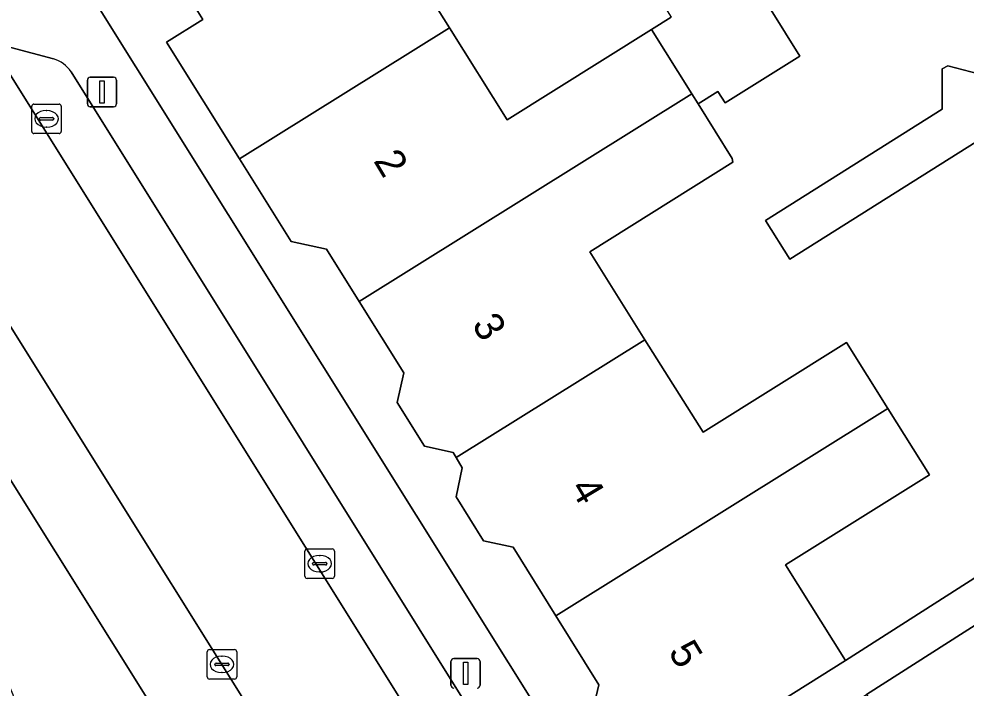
# Model space of a CAD drawing. Extents: x 159664 to 160323, y 385312 to 386115.
# Drawn here: x 159927.2 to 159959.3, y 386010.94 to 386033.62 of the extents above; entities that cross this region are included whole.
import ezdxf

# ---------------------------------------------------------------- set-up
doc = ezdxf.new("R2010")
doc.units = 0
for name, color, linetype in [('IMGEO_Erf', 7, 'Continuous'), ('IMGEO_Groenvoorziening', 7, 'Continuous'), ('IMGEO_Kolk', 7, 'Continuous'), ('IMGEO_Lichtmast', 7, 'Continuous'), ('IMGEO_Pand', 7, 'Continuous'), ('IMGEO_Pand_nummerreeks', 7, 'Continuous'), ('IMGEO_Parkeervlak_open', 7, 'Continuous'), ('IMGEO_Rijbaan_lokaal_open', 7, 'Continuous'), ('IMGEO_Voetpad_open', 7, 'Continuous')]:
    doc.layers.add(name, color=color, linetype=linetype)

msp = doc.modelspace()

# ---------------------------------------------------------------- linework, layer by layer
at = {"layer": 'IMGEO_Erf'}
for points in [[(159927.976, 386037.096), (159946.972, 386006.7), (159948.83, 386007.861), (159948.549, 386008.326), (159947.541, 386008.556), (159946.616, 386010.041), (159946.849, 386011.045), (159945.393, 386013.39), (159943.948, 386015.714), (159942.944, 386015.931), (159942.014, 386017.42), (159942.223, 386018.408), (159942.016, 386018.757), (159941.918, 386018.918), (159940.946, 386019.132), (159940.01, 386020.621), (159940.236, 386021.621), (159938.725, 386024.043), (159937.62, 386025.809), (159936.426, 386026.073), (159934.676, 386028.873), (159932.199, 386032.828), (159933.429, 386033.597), (159932.181, 386035.593)], [(159950.63, 386037.227), (159953.666, 386032.36), (159951.127, 386030.771), (159950.886, 386031.154), (159950.214, 386030.738), (159951.368, 386028.891), (159951.396, 386028.767), (159946.543, 386025.72), (159948.41, 386022.746), (159950.381, 386019.607), (159955.244, 386022.646), (159956.645, 386020.41), (159958.054, 386018.161), (159953.175, 386015.113), (159955.207, 386011.867), (159970.237, 386021.476)], [(159940.008, 386036.162), (159941.792, 386033.312), (159943.743, 386030.195), (159948.638, 386033.259), (159949.303, 386033.675)], [(159964.428, 386032.462), (159953.326, 386025.476), (159952.501, 386026.788), (159958.488, 386030.555), (159958.488, 386031.92), (159958.682, 386032.029), (159959.973, 386031.691)], [(159972.471, 386021.286), (159955.923, 386010.723), (159957.939, 386007.502), (159962.821, 386010.541)]]:
    msp.add_lwpolyline(points, dxfattribs=at)
at = {"layer": 'IMGEO_Groenvoorziening'}
msp.add_lwpolyline([(159955.282, 385972.677), (159935.869, 386003.671), (159924.707, 386021.493), (159923.616, 386016.481), (159926.674, 386011.449), (159926.994, 386010.725), (159927.155, 386009.956), (159927.153, 386009.17), (159926.987, 386008.402), (159926.418, 386007.571), (159928.912, 386004.426), (159932.034, 386000), (159933.824, 385997.462), (159936.786, 385992.325), (159938.156, 385989.949)], dxfattribs=at)
at = {"layer": 'IMGEO_Kolk'}
for p, q in [((159927.631, 386029.805), (159927.631, 386030.657)), ((159927.706, 386030.731), (159928.558, 386030.731)), ((159928.632, 386030.657), (159928.632, 386029.805)), ((159928.119, 386030.511), (159928.144, 386030.511)), ((159927.89, 386030.225), (159927.89, 386030.237)), ((159928.328, 386030.188), (159927.93, 386030.188)), ((159927.933, 386030.274), (159928.331, 386030.274)), ((159928.374, 386030.237), (159928.374, 386030.225)), ((159928.558, 386029.731), (159927.706, 386029.731)), ((159928.142, 386029.951), (159928.117, 386029.951)), ((159936.889, 386014.727), (159936.889, 386015.579)), ((159936.964, 386015.653), (159937.816, 386015.653)), ((159937.89, 386015.579), (159937.89, 386014.727)), ((159937.191, 386015.196), (159937.589, 386015.196)), ((159937.377, 386015.433), (159937.402, 386015.433)), ((159937.148, 386015.147), (159937.148, 386015.159)), ((159937.586, 386015.11), (159937.188, 386015.11)), ((159937.4, 386014.873), (159937.375, 386014.873)), ((159937.632, 386015.159), (159937.632, 386015.147)), ((159937.816, 386014.653), (159936.964, 386014.653)), ((159933.576, 386011.316), (159933.576, 386012.168)), ((159933.651, 386012.242), (159934.503, 386012.242)), ((159934.064, 386012.022), (159934.089, 386012.022)), ((159934.577, 386012.168), (159934.577, 386011.316)), ((159933.835, 386011.736), (159933.835, 386011.748)), ((159934.273, 386011.699), (159933.875, 386011.699)), ((159933.878, 386011.785), (159934.276, 386011.785)), ((159934.319, 386011.748), (159934.319, 386011.736)), ((159934.087, 386011.462), (159934.062, 386011.462)), ((159934.503, 386011.242), (159933.651, 386011.242))]:
    msp.add_line(p, q, dxfattribs=at)
for points in [[(159927.631, 386029.805), (159927.631, 386030.657)], [(159927.706, 386030.731), (159928.558, 386030.731)], [(159928.632, 386030.657), (159928.632, 386029.805)], [(159928.558, 386029.731), (159927.706, 386029.731)], [(159936.889, 386014.727), (159936.889, 386015.579)], [(159936.964, 386015.653), (159937.816, 386015.653)], [(159937.89, 386015.579), (159937.89, 386014.727)], [(159937.816, 386014.653), (159936.964, 386014.653)], [(159933.576, 386011.316), (159933.576, 386012.168)], [(159933.651, 386012.242), (159934.503, 386012.242)], [(159934.577, 386012.168), (159934.577, 386011.316)], [(159934.503, 386011.242), (159933.651, 386011.242)]]:
    msp.add_lwpolyline(points, dxfattribs=at)
for centre, radius, start, end in [((159927.708, 386030.655), 0.0765, 91.552, 178.448), ((159927.708, 386030.655), 0.0765, 91.552, 178.448), ((159928.556, 386030.655), 0.0765, 1.552, 88.448), ((159928.556, 386030.655), 0.0765, 1.552, 88.448), ((159927.93, 386030.234), 0.0403, 85.8775, 175.7526), ((159927.927, 386030.224), 0.0366, 178.938, 274.7102), ((159928.331, 386030.231), 0.043, 264.8664, 352.4533), ((159928.335, 386030.236), 0.0386, 1.7309, 96.639), ((159927.708, 386029.807), 0.0765, 181.552, 268.448), ((159927.708, 386029.807), 0.0765, 181.552, 268.448), ((159928.556, 386029.807), 0.0765, 271.552, 358.448), ((159928.556, 386029.807), 0.0765, 271.552, 358.448), ((159936.966, 386015.577), 0.0765, 91.552, 178.448), ((159936.966, 386015.577), 0.0765, 91.552, 178.448), ((159937.814, 386015.577), 0.0765, 1.552, 88.448), ((159937.814, 386015.577), 0.0765, 1.552, 88.448), ((159937.188, 386015.156), 0.0403, 85.8775, 175.7526), ((159937.593, 386015.158), 0.0386, 1.7309, 96.639), ((159937.185, 386015.146), 0.0366, 178.938, 274.7102), ((159937.589, 386015.153), 0.043, 264.8664, 352.4533), ((159936.966, 386014.729), 0.0765, 181.552, 268.448), ((159936.966, 386014.729), 0.0765, 181.552, 268.448), ((159937.814, 386014.729), 0.0765, 271.552, 358.448), ((159937.814, 386014.729), 0.0765, 271.552, 358.448), ((159933.653, 386012.166), 0.0765, 91.552, 178.448), ((159933.653, 386012.166), 0.0765, 91.552, 178.448), ((159934.501, 386012.166), 0.0765, 1.552, 88.448), ((159934.501, 386012.166), 0.0765, 1.552, 88.448), ((159933.875, 386011.745), 0.0403, 85.8775, 175.7526), ((159933.872, 386011.735), 0.0366, 178.938, 274.7102), ((159934.276, 386011.742), 0.043, 264.8664, 352.4533), ((159934.28, 386011.747), 0.0386, 1.7309, 96.639), ((159933.653, 386011.318), 0.0765, 181.552, 268.448), ((159933.653, 386011.318), 0.0765, 181.552, 268.448), ((159934.501, 386011.318), 0.0765, 271.552, 358.448), ((159934.501, 386011.318), 0.0765, 271.552, 358.448)]:
    msp.add_arc(centre, radius, start, end, dxfattribs=at)
for centre, major_axis, ratio, start_param, end_param in [((159928.118, 386030.231), (-0.387, 0.002), 0.722429, 4.712389, 7.853982), ((159928.143, 386030.231), (-0.39, 0.002), 0.717154, 1.570796, 4.712389), ((159937.376, 386015.153), (-0.387, 0.002), 0.722429, 4.712389, 7.853982), ((159937.401, 386015.153), (-0.39, 0.002), 0.717154, 1.570796, 4.712389), ((159934.063, 386011.742), (-0.387, 0.002), 0.722429, 4.712389, 7.853982), ((159934.088, 386011.742), (-0.39, 0.002), 0.717154, 1.570796, 4.712389)]:
    msp.add_ellipse(centre, major_axis=major_axis, ratio=ratio, start_param=start_param, end_param=end_param, dxfattribs=at)
at = {"layer": 'IMGEO_Lichtmast'}
for p, q in [((159929.615, 386031.639), (159930.405, 386031.639)), ((159930.405, 386031.639), (159929.615, 386031.639)), ((159929.515, 386030.739), (159929.515, 386031.539)), ((159929.515, 386031.539), (159929.515, 386030.739)), ((159930.505, 386031.539), (159930.505, 386030.739)), ((159930.505, 386030.739), (159930.505, 386031.539)), ((159930.405, 386030.639), (159929.615, 386030.639)), ((159929.615, 386030.639), (159930.405, 386030.639)), ((159941.839, 386011.038), (159941.839, 386011.838)), ((159941.839, 386011.838), (159941.839, 386011.038)), ((159941.939, 386011.938), (159942.729, 386011.938)), ((159942.729, 386011.938), (159941.939, 386011.938)), ((159942.829, 386011.838), (159942.829, 386011.038)), ((159942.829, 386011.038), (159942.829, 386011.838))]:
    msp.add_line(p, q, dxfattribs=at)
for points in [[(159929.935, 386031.514), (159930.085, 386031.514), (159930.085, 386030.764), (159929.935, 386030.764), (159929.935, 386031.514)], [(159942.259, 386011.813), (159942.409, 386011.813), (159942.409, 386011.063), (159942.259, 386011.063), (159942.259, 386011.813)]]:
    msp.add_lwpolyline(points, dxfattribs=at)
for centre, start, end in [((159929.615, 386031.539), 90, 180), ((159929.615, 386031.539), 90, 180), ((159930.405, 386031.539), 0, 90), ((159930.405, 386031.539), 360, 90), ((159929.615, 386030.739), 180, 270), ((159929.615, 386030.739), 180, 270), ((159930.405, 386030.739), 270, 0), ((159930.405, 386030.739), 270, 0), ((159941.939, 386011.838), 90, 180), ((159941.939, 386011.838), 90, 180), ((159942.729, 386011.838), 0, 90), ((159942.729, 386011.838), 360, 90), ((159941.939, 386011.038), 180, 270), ((159941.939, 386011.038), 180, 270), ((159942.729, 386011.038), 270, 0), ((159942.729, 386011.038), 270, 0)]:
    msp.add_arc(centre, 0.1, start, end, dxfattribs=at)
at = {"layer": 'IMGEO_Pand'}
for points in [[(159951.127, 386030.771), (159953.666, 386032.36), (159950.63, 386037.227), (159954.297, 386039.517), (159950.314, 386045.885), (159949.828, 386046.619), (159945.611, 386043.982), (159946.379, 386042.753), (159944.387, 386041.507), (159949.303, 386033.675), (159948.638, 386033.259), (159950.002, 386031.077), (159950.214, 386030.738), (159950.886, 386031.154)], [(159934.676, 386028.873), (159941.792, 386033.312), (159940.008, 386036.162), (159944.246, 386038.815), (159942.32, 386041.892), (159932.181, 386035.593), (159933.429, 386033.597), (159932.199, 386032.828)], [(159950.002, 386031.077), (159948.638, 386033.259), (159943.743, 386030.195), (159941.792, 386033.312), (159934.676, 386028.873), (159936.426, 386026.073), (159937.62, 386025.809), (159938.725, 386024.043)], [(159946.543, 386025.72), (159951.396, 386028.767), (159951.368, 386028.891), (159950.214, 386030.738), (159950.002, 386031.077), (159938.725, 386024.043), (159940.236, 386021.621), (159940.01, 386020.621), (159940.946, 386019.132), (159941.918, 386018.918), (159942.016, 386018.757), (159948.41, 386022.746)], [(159955.244, 386022.646), (159950.381, 386019.607), (159948.41, 386022.746), (159942.016, 386018.757), (159942.223, 386018.408), (159942.014, 386017.42), (159942.944, 386015.931), (159943.948, 386015.714), (159945.393, 386013.39), (159956.645, 386020.41)], [(159953.175, 386015.113), (159958.054, 386018.161), (159956.645, 386020.41), (159945.393, 386013.39), (159946.849, 386011.045), (159946.616, 386010.041), (159947.541, 386008.556), (159948.549, 386008.326), (159948.83, 386007.861), (159955.207, 386011.867)]]:
    msp.add_lwpolyline(points, close=True, dxfattribs=at)
at = {"layer": 'IMGEO_Parkeervlak_open'}
for points in [[(159925.856, 386033.371), (159959.016, 385980.344)], [(159928.363, 386032.267), (159926.923, 386032.643)], [(160007.649, 385905.881), (159928.962, 386031.821)]]:
    msp.add_lwpolyline(points, dxfattribs=at)
msp.add_arc((159928.06, 386031.235), 1.075, 33.0138, 73.6454, dxfattribs=at)
at = {"layer": 'IMGEO_Rijbaan_lokaal_open'}
msp.add_lwpolyline([(159959.016, 385980.344), (159925.856, 386033.371), (159924.811, 386035.12), (159920.972, 386032.678), (159955.159, 385977.993)], close=True, dxfattribs=at)
at = {"layer": 'IMGEO_Voetpad_open'}
for points in [[(160035.946, 385864.298), (160011.524, 385903.327), (160009.458, 385906.629), (159986.636, 385943.101), (159975.855, 385960.448), (159975.052, 385961.74), (159971.661, 385967.195), (159947.685, 386005.559), (159946.972, 386006.7), (159927.976, 386037.096), (159924.811, 386035.12), (159925.856, 386033.371)], [(159920.972, 386032.678), (159918.634, 386031.189), (159922.172, 386025.541), (159924.707, 386021.493), (159935.869, 386003.671), (159955.282, 385972.677), (159957.008, 385971.838)], [(159956.151, 385976.381), (159955.159, 385977.993), (159920.972, 386032.678)], [(159926.923, 386032.643), (159928.363, 386032.267)], [(159959.973, 386031.691), (159958.682, 386032.029), (159958.488, 386031.92), (159958.488, 386030.555), (159952.501, 386026.788), (159953.326, 386025.476), (159964.428, 386032.462)], [(159928.962, 386031.821), (160007.649, 385905.881), (160007.996, 385906.094), (160010.404, 385902.292), (160010.038, 385902.057), (160043.232, 385848.929)], [(159970.237, 386021.476), (159955.207, 386011.867), (159948.83, 386007.861), (159946.972, 386006.7), (159947.685, 386005.559), (159949.555, 386006.728), (159955.923, 386010.723), (159972.471, 386021.286)]]:
    msp.add_lwpolyline(points, dxfattribs=at)
msp.add_arc((159928.06, 386031.235), 1.075, 33.0138, 73.6454, dxfattribs=at)

# ---------------------------------------------------------------- texts
at = {"layer": 'IMGEO_Pand_nummerreeks'}
for s, rotation, p in [('2', 300.9759, (159939.194, 386028.809)), ('3', 300.9739, (159942.526, 386023.26)), ('4', 300.9759, (159945.854, 386017.714)), ('5', 300.9759, (159949.184, 386012.167))]:
    msp.add_text(s, height=1, rotation=rotation, dxfattribs=at).set_placement(p)

doc.saveas('drawing.dxf')
